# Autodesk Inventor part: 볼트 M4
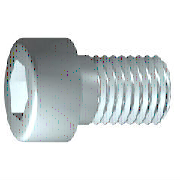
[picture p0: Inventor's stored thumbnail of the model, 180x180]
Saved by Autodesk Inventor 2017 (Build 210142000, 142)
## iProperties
IsCustomPart: 0
Created: 2014-10
Part Number: 볼트 M4
Material: 강철, 연강
Description: 6각머리 태핑 나사
Document SubType Name: Modeling
Standard: KS B 1003
Designer: KYOUNG IL JANG
Standards Organization: KS
Language: ko-KR
Size Designation: M 4 x 10
Categories: <MemberInstance><Categories><Category DisplayName="조임쇠" InternalName="e4da775c-781d-43d5-af7c-5136215cf5a6" Mnemonic="FSTN"><Category DisplayName="볼트" InternalN
Density: 7.86 g/cm^3
Mass: 2.0371 g
Surface Area: 3.0572 cm^2
Volume: 0.259174 cm^3
Appearance: 강철 - 광택
Author: SeoGD™ [www.esajin.kr]
Revision Number: 1
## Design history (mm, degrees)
sketch "스케치1"
  geometry: L1 (-1, 0)-(10, 0); L2 (10, 0)-(10, 2); L3 (10, 2)-(1.75, 2); L4 (1.75, 2)-(1.32, 2); L5 (1.32, 2)-(0, 2); L6 (0, 2)-(0, 3.5); L7 (0, 3.5)-(-4, 3.5); L8 (-4, 3.5)-(-4, 1.732); L9 (-4, 1.732)-(-2, 1.732); L10 (-2, 1.732)-(-1, 0); L11 (-6.8, 0)-(12.8, 0) reference; L12 (0, -0.7)-(0, 4.2) reference; L13 (1.75, 2)-(0, 2)
  constraints: 22 end point, 6 parallel, 2 collinear, 2 perpendicular, 1 horizontal, 1 point on line
  dimensions: "d1" = 8.25 distance from line of L3.end L2 (= GEL); "d2" = 0.42952 distance of L4.end L3.end (computed from GAL); "d3" = 4 distance between parallel lines of L8 L6 (= KOH); "d4" = 2 distance of L8.end L9.end (= INTI); "d5" = 60 deg angle of L10 L1; "d6" = 4 diameter of L3 L1 (= GD); "d7" = 4 diameter of L5 L1 (= BDM); "d8" = 3.4641 diameter of L9 L1 (= 1.1547 x SW); "d9" = 7 diameter of L7 L1 (= KOD); "d26" = 10 distance between parallel lines of L12 L2 (= NLG)
revolve "본체" sketch "스케치1" stored, may be unused: angle "d10" = 90 deg
sketch "스케치2"
  geometry: L1 (0, -4.9)-(0, 4.9) reference; L2 (-4.9, 0)-(4.9, 0) reference; L3 (1.732, 0)-(0.866, -1.5); L4 (0.866, -1.5)-(-0.866, -1.5); L5 (-0.866, -1.5)-(-1.732, 0); L6 (-1.732, 0)-(-0.866, 1.5); L7 (-0.866, 1.5)-(0.866, 1.5); L8 (0.866, 1.5)-(1.732, 0); 2 further points
  constraints: 12 end point, 1 coincident, 1 horizontal alignment, 1 point on line, 12 other
extrude "슬롯" join sketch "스케치2" stored distance "d11" = 10; taper "d12" = 0 deg
workplane "Work Plane1"
fillet "Fillet2" dims "d30" = 0.1 (= R)
body "Solid1"
fillet "모깎기1" dims "d17" = 0.4 (= RR)
feature "스레드" dims "d13" = 8.25 (= GEL), "d14" = 0
chamfer "모따기1" distance "d15" = 0.42941 (= -0.5 x SPD + 0.5 x GD); stored, may be unused: second distance "d16" = 0.42941 (= GUL), angle "d27" = 45 deg
other parameters: "GD" = 4 (= NND) [user parameter; used in 2 equation terms], "NLG" = 10 [user parameter; used in 1 equation term], "GEL" = 8.25 [user parameter; used in 2 equation terms], "KOD" = 7 [user parameter; used in 1 equation term], "KOH" = 4 [user parameter; used in 1 equation term], "INTI" = 2 [user parameter; used in 1 equation term], "GAL" = 0.42941 (= 0.61345 x PTC) [user parameter; used in 1 equation term], "GUL" = 0.42941 (= 0.61345 x PTC) [user parameter; used in 1 equation term], "BDM" = 4 (= NND) [user parameter; used in 1 equation term], "SW" = 3 [user parameter; used in 2 equation terms], "RR" = 0.4 [user parameter; used in 1 equation term], "SPD" = 3.14117 (= NND - 1.2269 x PTC) [user parameter; used in 1 equation term], "d19" = 0, "d28" = 0, "d29" = 0, "R" = 0.1 [user parameter; used in 1 equation term], "PHH" = 0.2 [user parameter], "GD1" = 3.14117 (= THREADDIA - 1.2269 x PTC) [user parameter], "THREADDIA" = 4 [user parameter; used in 1 equation term], "FAWI" = 45 deg [user parameter], "TPU" = 14.28571 (computed from PTC) [user parameter], "PTC" = 0.7 [user parameter; used in 5 equation terms], "NND" = 4 [user parameter; used in 3 equation terms], "TOA" = 30 deg [user parameter], "E0" = 3.465 (= 1.155 x SW) [user parameter]
